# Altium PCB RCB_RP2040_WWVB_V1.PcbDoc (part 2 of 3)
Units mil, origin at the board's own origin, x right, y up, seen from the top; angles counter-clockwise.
Board outline 1250.1 x 2647.64 mil, 10 copper layers (L01-TOP, L02-GND, L03-SIG, L04-GND, L05-PWR, L06-PWR, L07-GND, L08-SIG, L09-GND, L10-BOT), stack 62.1 mil thick; 224 components, 123 nets, 635 pads, 542 vias.
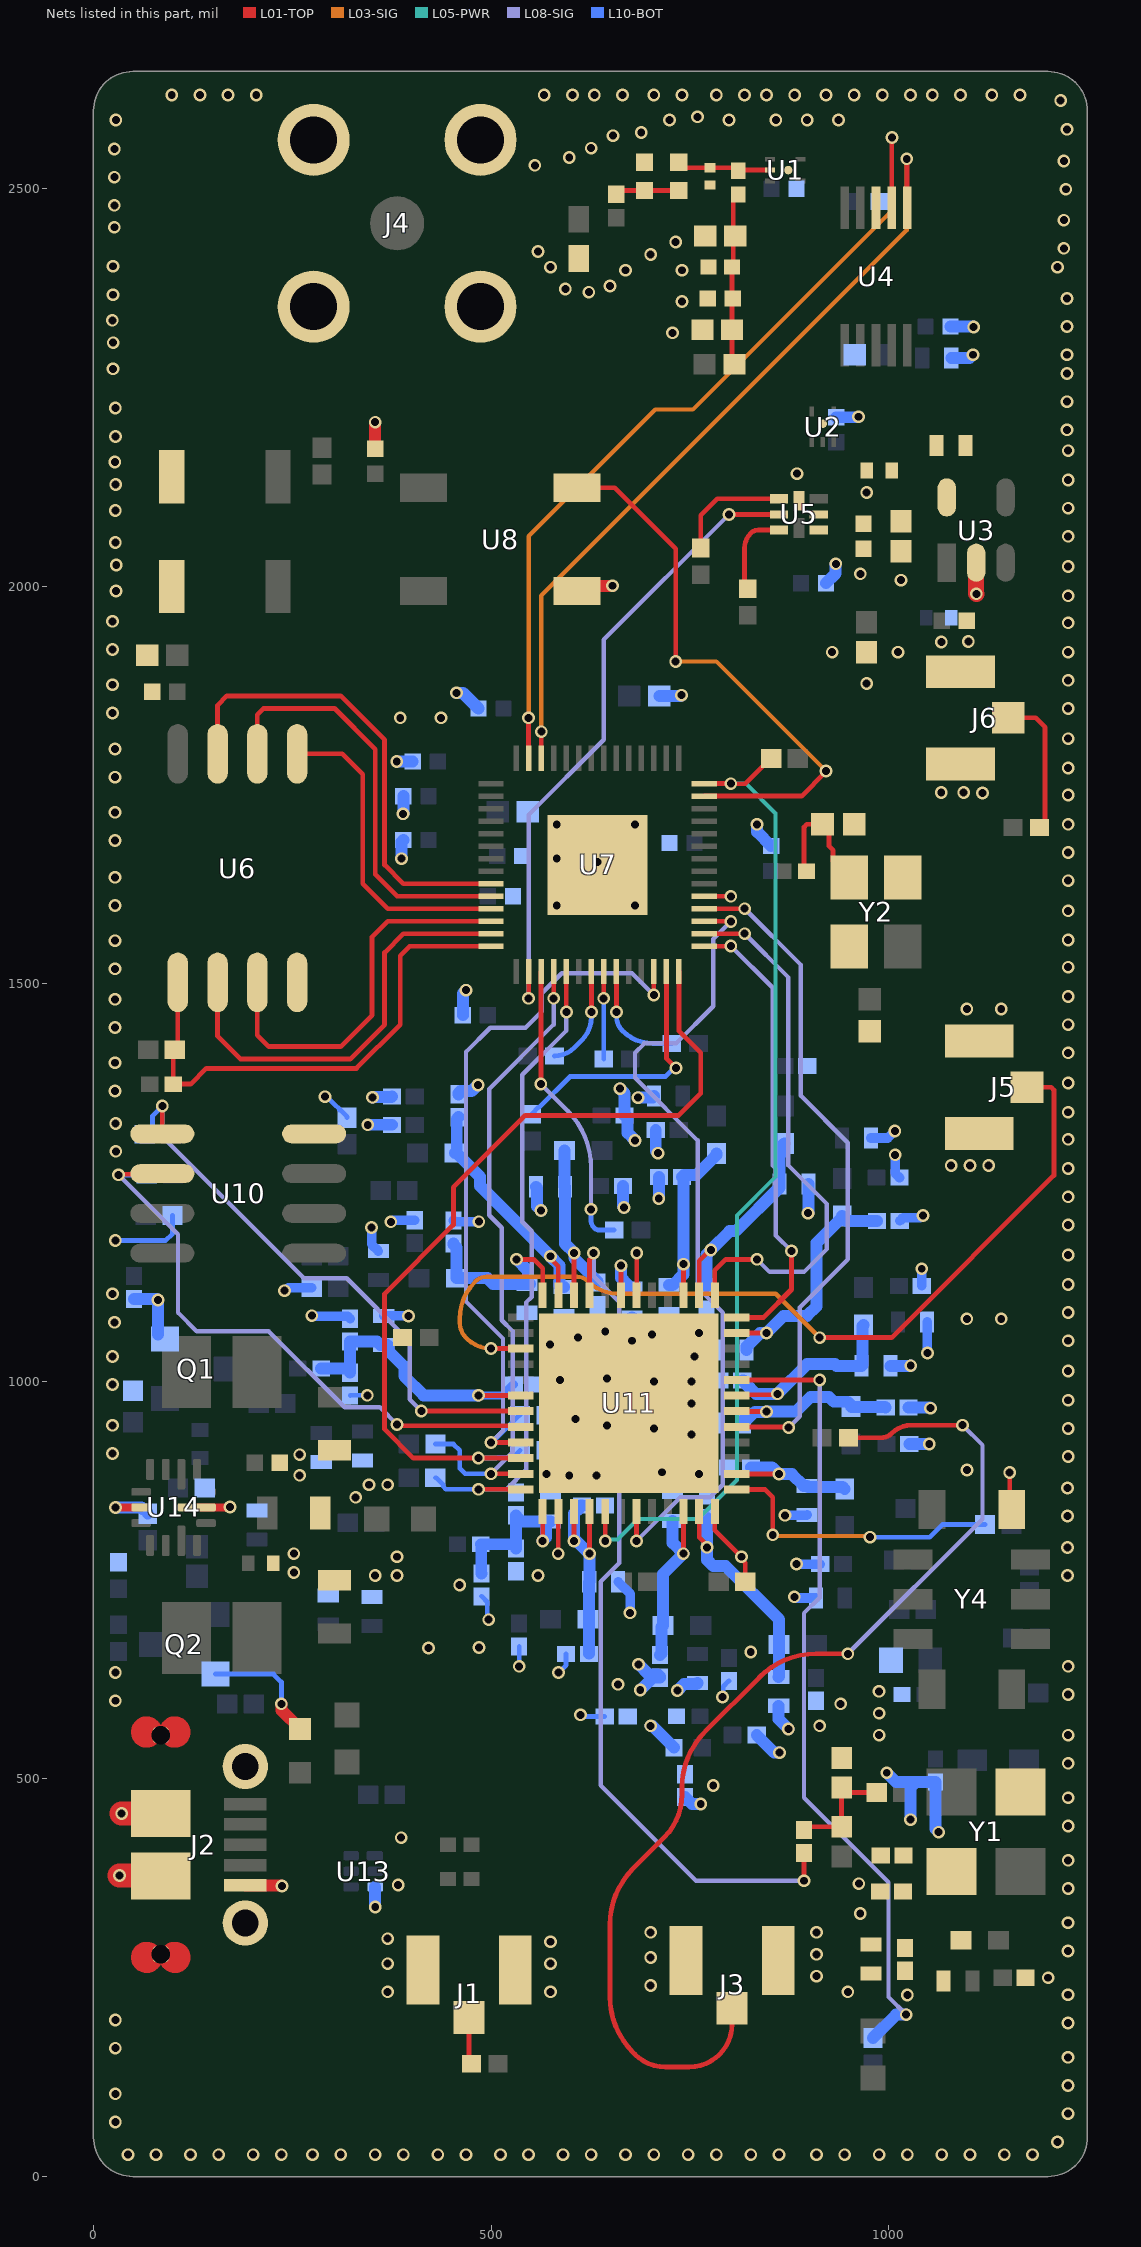
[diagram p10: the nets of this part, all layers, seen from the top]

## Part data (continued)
C8 C11 C15 C18 C28 C31 C49: library part CMP-14477-000104-2, "None", Capacitance=1uF, Case Code (Imperial)=0402, Case Code (Metric)=1005, Dielectric=X5R, Max Operating Temperature=85°C, Min Operating Temperature=-55°C, Package Quantity=1, Tolerance=10%, Voltage Rating=16V
C10 C14 C36 C37: library part CMP-2000-05997-2, "CAP CER 4.7UF 10V X5R 0402", Capacitance=4.7uF, Case Code (Imperial)=0402, Case Code (Metric)=1005, Dielectric=X5R, Dielectric Material=Ceramic, Max Operating Temperature=85°C, Min Operating Temperature=-55°C, Package Quantity=10000, Tolerance=10%, Voltage Rating=10V
C21 C23 C25 C26 C27 C55 C59 C60 C63 C65 C66 C67 C69 C70 C72 C74 C75 C76 C78 C79 C81 C82 C83 C85 C86 C88 C89 C91 C93 C95 C96 C98 C99 C101 C103 C106 C108 C110 C111 C113 C115: library part CMP-2008-02519-2, "General Purpose Ceramic Capacitor, 0402, 100nF, 10%, X7R, 15%, 25V", Capacitance=100nF, Case Code (Imperial)=0402, Case Code (Metric)=1005, Dielectric=X7R, Max Operating Temperature=125°C, Min Operating Temperature=-55°C, Package Quantity=1, Tolerance=10%, Voltage=25V
C38 C45 C48: library part CMP-2000-05441-1, "Chip Capacitor, 22 uF, +/- 20%, 10 V, -55 to 85 degC, 0603 (1608 Metric), RoHS, Tape and Reel", Capacitance=22µF, Manufacturer=TDK, Operating Temperature=-55degC~85degC, Package / Case=0603(1608Metric), Package Description="2-Pin Surface Mount Device, Body 1.6 x 0.8 mm", Package Reference=603, PCN Part Number=MLCCPartNumberChange30/Nov/2012, Ratings=-, Standard Package=1, Temperature Coefficient=X5R, Tolerance=±20%, Voltage - Rated=10V
C52 C53: library part CMP-2100-03590-1, "Chip Capacitor, 22 pF, +/- 5%, 50 V, -55 to 125 degC, 0402 (1005 Metric), RoHS, Tape and Reel", Capacitance=22pF, Case Code (Imperial)=0402, Case Code (Metric)=1005, Dielectric=C0G, Dielectric Material=Ceramic, Insulation Resistance=100GR, Manufacturer=Yageo, Max Operating Temperature=125degC, Min Operating Temperature=-55degC, Package Description="2-Pin Surface Mount Device, Body 1 x 0.5 mm", Package Quantity=1, Temperature Coefficient=30ppm/degC, Tolerance=5%, Voltage Rating=50V
C54 C57: library part CMP-2000-05393-2, "Multilayer Ceramic Capacitors 100nF ±10% 50V X7R SMD 0402", Capacitance=100nF, Case Code (Imperial)=0402, Case Code (Metric)=1005, Dielectric=X7R, Dielectric Material=Ceramic, Max Operating Temperature=125°C, Min Operating Temperature=-55°C, Package Quantity=1, Tolerance=10%, Voltage=50V
C56: library part CMP-13271-004224-1, "Cap Ceramic 10uF 25V X5R ±20% Pad SMD 0603 +85°C T/R", Capacitance=10uF, Case Code (Imperial)=0603, Case Code (Metric)=1608, Dielectric=X5R, Max Operating Temperature=85°C, Min Operating Temperature=-55°C, Package Quantity=1, Tolerance=20%, Voltage Rating=25V
C61: library part CMP-2008-02907-1, Manufacturer="AVX Interconnect / Elco", Part Number=04025C222JAT2A
C105: library part CMP-2000-06226-4, "Multilayer Ceramic Capacitor 10uF 16V X5R 20% SMD 0603 T/R", Capacitance=10uF, Case Code (Imperial)=0603, Case Code (Metric)=1608, Dielectric=X5R, Max Operating Temperature=85°C, Min Operating Temperature=-55°C, Package Quantity=1, Tolerance=20%, Voltage Rating=16V
D1 D3 D4: library part CMP-22017-000005-2, "LED GREEN CLEAR CHIP SMD", Case Code (Imperial)=0603, Case Code (Metric)=1608, Color=Green, Forward Current=30mA, Forward Voltage=2.1V, Lens Color=Colorless, Max Operating Temperature=85°C, Min Operating Temperature=-55°C, Package Quantity=1, Power Dissipation=100mW, Reverse Voltage=5V, Test Current=10mA, Voltage=2V
D2: library part CMP-1055-00495-1, "Schottky Barrier Diode, 2-Pin SOD-923, Pb-Free, Tape and Reel", Manufacturer="On Semiconductor"
D5: library part CMP-08607-000011-1, "TVS DIODE 14V 40V 0402", Breakdown Voltage=14V, Capacitance=0.25pF, Clamping Voltage=40V, Manufacturer="Littelfuse Inc.", Package=PESD0402, Temperature="-55°C to +125°C", Temperature Range High=+125°C, Temperature Range Low=-55°C
FB2: library part CMP-0220-00171-2, "FERRITE BEAD 300 OHM 0603 1LN", Case Code (Imperial)=0603, Case Code (Metric)=1608, Case/Package=SMD/SMT, Current Rating=2A, DC Resistance (DCR)=150mR, Inductance=18nH, Max Operating Temperature=125°C, Min Operating Temperature=-55°C, Package Quantity=1, Test Frequency=100MHz, Tolerance=25%
J1 J3 J5 J6: library part CMP-2000-05152-3, "CONN U.FL RCPT STR 50 OHM SMD", Dielectric Material=Polymer, Frequency=6GHz, Housing Color=Beige, Insulation Resistance=500MR, Max Operating Temperature=90°C, Min Operating Temperature=-40°C, Package Quantity=2500
J2: library part CMP-2000-05827-1, "Micro-USB B Receptacle, Right Angle, Bottom Mount, Surface Mount, with Solder Tabs, -30 to 85 degC, 5-Pin USB, RoHS, Tape and Reel", Manufacturer=Molex, Package Description="5-Leads USB, Micro B, Body 7.5 x 5 mm, Pitch 0.65 mm", Package Reference=MICRO-B, Package Version="Rev. F, 12/2012", Standard Package=1, Voltage - Max=30V
J4: library part CMP-02754-000007-1, "CONN SMA JACK STR 50 OHM SMD", Case/Package=SMA, Dielectric Material=PTFE, Housing Color=Gold, Max Frequency=20GHz, Max Operating Temperature=125°C, Min Operating Temperature=-65°C, Voltage Rating=335V
L1: library part CMP-06042-003301-1, "Multilayer type Inductor for Automotive 47nH ±5% 0.72Ω 300mA 0402", Case Code (Imperial)=0402, Case Code (Metric)=1005, Current Rating=200mA, DC Resistance (DCR)=720mR, Inductance=47nH, Max Operating Temperature=125°C, Min Operating Temperature=-55°C, Package Quantity=10000, Self Resonant Frequency=1GHz, Test Frequency=100MHz, Tolerance=5%
L2 L3 L4 L5 L6 L7 L8 L11 L12 L13 L14 L15 L16: library part CMP-0220-00137-1, "SMD EMI Suppression Ferrite Bead WE-CBF, Z = 220 Ohm"
L9 L10: library part CMP-06042-015149-1, "Shielded Wirewound Inductor 0.47uH 20% 4000mA 0.027Ω 1008 (2520)"
Q1 Q2: library part CMP-1058-00766-2, "MOSFET N-CH 60V 320MA SOT-23", Case/Package=SOT-23-3, Continuous Drain Current (ID)=320mA, Drain to Source Breakdown Voltage=60V, Drain to Source Resistance=1.6R, Gate to Source Voltage (Vgs)=20V, Input Capacitance=24.5pF, Max Operating Temperature=150°C, Max Power Dissipation=420mW, Min Operating Temperature=-55°C, Package Quantity=1, Power Dissipation=300mW, Threshold Voltage=2.3V
R1 R2 R48: library part CMP-2002-08277-1, Manufacturer="Vishay Dale", Part Number=CRCW04021K00FKTD
R3 R4 R5 R8: library part CMP-2002-06458-1, Manufacturer=Panasonic, Part Number=ERJ-U02F1000X
R6 R33 R34 R35 R36 R37 R38 R39 R40 R41 R42 R44 R79 R97: library part CMP-2002-06457-1, Manufacturer=Panasonic, Part Number=ERJ-U020R00X
R7 R26: library part CMP-2002-04448-1, Manufacturer="KOA Speer", Part Number=RK73H1ETTP49R9F
R9 R13 R53 R54 R56 R77: library part CMP-2002-04694-1, Manufacturer=Bourns, Part Number=CR0402-FX-1002GLF
R10 R14: library part CMP-2002-04692-1, Manufacturer=Bourns, Part Number=CR0402-FX-1001GLF
R11 R12: library part CMP-2002-07055-1, Manufacturer="Yageo / Phycomp", Part Number=RC0402FR-0727RL
R15: library part CMP-2002-05709-1, Manufacturer="TE Connectivity / AMP", Part Number=CRG0402F20K
R16 R17 R71: library part CMP-2002-05853-1, Manufacturer=Panasonic, Part Number=ERA-2AED331X
R18 R19 R20 R21 R22 R23 R24 R25 R27 R28 R29 R30 R31 R32 R45 R46 R49 R50 R95 R96: library part CMP-2002-05217-1, Manufacturer=Bourns, Part Number=CR0402-FX-4701GLF
R47 R51 R52: library part CMP-2002-04569-1, Manufacturer="KOA Speer", Part Number=RK73Z1ETTP
R58: library part CMP-1011-00697-1, "45K3 0.063W 1% 0402 (1005 Metric)  SMD", Case-EIA=0402, Case-Metric=1005, Power="0.063 W", Tolerance="1 %"
R98: library part CMP-2002-00253-3, "Chip Resistor, 8.06 KOhm, +/- 1%, 63 mW, -55 to 155 degC, 0402 (1005 Metric), RoHS, Tape and Reel", Case Code (Imperial)=0402, Case Code (Metric)=1005, Manufacturer="Basic Passives", Max Operating Temperature="155 degC", Min Operating Temperature="-55 degC", Package Quantity=10000, PartNumber=CRCW04028K06FKED, Power Rating="63 mW", Resistance="8.06 KOhm", Tolerance=1%, Voltage Rating="50 V"
SW1 SW2: library part CMP-2100-03586-2, "SWITCH TACTILE SPST-NO 0.05A 12V", Contact Current Rating=50mA, Contact Resistance=100mR, Insulation Resistance=100MR, Max Operating Temperature=70°C, Max Voltage Rating (DC)=12V, Min Operating Temperature=-25°C, Operating Force=1.5N, Package Quantity=1, Ratings="Dust Proof"
U1 U2: library part CMP-85923-000009-1, "IC RF SWITCH SPDT 6GHZ 6MLPD", Max Operating Temperature=90°C, Min Operating Temperature=-40°C, Test Frequency=2.5GHz
U3: library part CMP-79890-000003-1, "IC REG LIN 3.3V 600MA TSOT23-5", Case/Package=SOT-23-5, Dropout Voltage=530mV, Max Input Voltage=5.5V, Max Operating Temperature=85°C, Min Operating Temperature=-40°C, Min Output Voltage=3.3V, Output Current=600mA, Power Supply Rejection Ratio (PSRR)=75dB, Quiescent Current=4uA
U4: "No Description Available", Mfr_Name="Analog Devices Inc"
U5: "No Description Available", Mfr_Name="Texas Instruments"
U6: library part CMP-2000-05005-1, "3V 128M-Bit Serial Flash Memory with Dual/Quad SPI & QPI, 2.7 to 3.6 V, -40 to 85 degC, 8-Pin SOIC, RoHS, Tape and Reel", Manufacturer=Winbond, Operating Supply Voltage (Max)=3.6V, Operating Supply Voltage (Min)=2.7V, Operating Supply Voltage (Typ)=3/3.3V, Operating Temp Range=-40Cto85C, Operating Temperature (Max)=85C, Operating Temperature (Min)=-40C, Operating Temperature Classification=Industrial, Package Description="8-Pin Small Outline Integrated Circuit, Body 5.28 x 5.28 mm, Pitch 1.27 mm", Package Reference=SS-8, Package Type=SOICW, Program/Erase Volt (Typ)=2.7to3.6V, Supply Current=20mA
U7: "No Description Available", Mfr_Name="Raspberry Pi"
U8: library part CMP-2000-05026-1, "Intelligent Control LED Integrated Light Source, 3.5 to 5.3 V, -25 to 80 degC, 4-Pin SMD, RoHS, Tape and Reel", Color=Red,Green,Blue(RGB), Manufacturer=Adafruit-Industries-LLC, Package Description="4-Pin Surface Mount Device, Body 5 x 5 mm"
U10: library part CMP-0159-01024-1, "1024K bits I2C™ Serial EEPROM, 2.5 to 5.5 V, 400 kHz, -40 to 85 degC, 8-pin SOIC (SN8), Tube", Manufacturer=Microchip
U11: "No Description Available", Mfr_Name="Renesas Electronics"
U13: library part CMP-0326-00032-3, "Low-Capacitance + / - 15 kV ESD-Protection Array for High-Speed Data Interfaces, 3 Channels, -40 to +85 degC, 6-pin SON (DRY), Green (RoHS & no Sb/Br)", Breakdown Voltage(Min)(V)=11, IO Capacitance(Typ)(pF)=1.5, IO Leakage Current(nA)=Jan-00, Manufacturer="Texas Instruments"
U14: library part CMP-04918-000654-1, "Adjustable-Frequency Dual Step-Down Converter, 2.7-6V VIN, 0.6-5.5V 2A VOUT, VQFN-HR14"
Y1: library part CMP-25159-259584-1, "MEMS OSC TCXO 40.0000MHZ LVCMOS", Case/Package=SMD/SMT, Frequency=40MHz, Frequency Stability=5ppm, Max Operating Temperature=70°C, Max Supply Current=33mA, Min Operating Temperature=-20°C
Y2: library part CMP-2000-05039-3, "Crystal 12MHz ±20ppm (Tol) ±30ppm (Stability) 18pF FUND 120Ω 4-Pin SMD T/R", Case/Package=CSMD, ESR (Equivalent Series Resistance)=120R, Frequency=12MHz, Frequency Stability=30ppm, Frequency Tolerance=20ppm, Load Capacitance=18pF, Max Operating Temperature=85°C, Min Operating Temperature=-40°C, Operating Frequency="12 MHz", Package Quantity=1000
Y4: library part CMP-OSC-00029-2, "OSC, MEMS, STRATUM 3E, 10.000MHZ, 10PPB STAB, LVCMOS, 3.3V, O/P EN, 7.0X5.0X2.2MM, CQFN-10", Case/Package="10 Lead QFN", Frequency="10 MHz", Frequency Stability="±10 ppb", Manufacturer=SiTime, Manufacturer Part Number=SiT5501AI-WU033JH-10.000000, Max Operating Temperature=70°C, Min Operating Temperature=-20°C, Voltage - Supply="3.3 V"

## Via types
v1: diameter 16, hole 10, L01-TOP to L10-BOT, tented both sides, 542 vias

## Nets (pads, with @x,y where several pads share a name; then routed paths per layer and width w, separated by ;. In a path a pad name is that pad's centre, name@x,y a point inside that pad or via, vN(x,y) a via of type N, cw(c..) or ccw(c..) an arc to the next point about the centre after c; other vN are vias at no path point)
ADC_AVDD: C13.1 C14.1 C15.1 C16.1 U3.5 U5.6
ADC_SDO: U5.2 U7.2 | length 809.6
  L01-TOP w6: v1(547.26,1481.95) 547.34,1482.03 U7.2@547.34,1515.56 ; v1(799.21,2090.55) U5.2@862.2,2090.55
  L08-SIG w5.5: v1(547.26,1481.95) 547.26,1712.61 641.73,1807.09 641.73,1933.07 v1(799.21,2090.55)
AMP_DIN: U4.2 U7.41 | length 1086.1
  L01-TOP w6: v1(547.24,1834.65) 547.31,1834.57 547.31,1783.68 U7.41@547.39,1783.61 ; U4.2@1003.94,2476.51 1003.94,2564.07 v1(1004.35,2564.48)
  L03-SIG w5.5: v1(547.24,1834.65) 547.24,2062.99 706.69,2222.44 753.94,2222.44 1004.35,2472.85 v1(1004.35,2564.48)
AMP_SCLK: U4.1 U7.40 | length 1006.2
  L01-TOP w6: U7.40@563.18,1783.65 563.18,1817.18 v1(563.26,1817.27) ; v1(1022.91,2537.83) 1023.26,2537.47 1023.26,2476.87 U4.1@1023.62,2476.51
  L03-SIG w5.5: v1(563.26,1817.27) 563.26,1988.46 1022.91,2448.1 v1(1022.91,2537.83)
DPLL_CLKIN0_N: J5.1 U11.3 | length 1138.7
  L01-TOP w6: v1(500,1041.34) U11.3@537.23,1041.34 ; v1(913.39,1055.12) 1003.94,1055.12 1207.98,1259.16 1207.98,1366.56 1204.46,1370.08 J5.1@1174.21,1370.08
  L03-SIG w5.5: 480.32,1125.98 cw(c494.01,1112.29) 494.01,1131.66 608.35,1131.66 cw(c608.35,1112.29) 622.05,1125.98 ccw(c660.07,1164) 660.07,1110.24 858.27,1110.24 v1(913.39,1055.12) ; 482.65,1127.98 479.87,1125.2 ccw(c526.33,1078.74) 460.63,1078.74 460.63,1074.13 ccw(c487.51,1074.13) 468.5,1055.12 469.76,1053.87 ccw(c500,1084.11) v1(500,1041.34)
DPLL_CLKIN0_P: R34.1
DPLL_CLKIN1_N: J1.1 R44.1 | length 59.3
  L01-TOP w6: J1.1@472.44,199.8 472.44,144.69 R44.1@475.39,141.73
DPLL_CLKIN1_P: R36.1 U7.13 | length 332.1
  L01-TOP w6: U7.13@720.73,1515.58 720.61,1515.46 720.61,1406.35 v1(732.79,1394.18)
  L10-BOT w6: R36.1@551.85,1336.02 551.85,1337 559.68,1344.83 560.66,1344.83 599.36,1383.52 719.43,1383.52 730.08,1394.18 v1(732.79,1394.18)
DPLL_CLKOUT8_N: R33.2 U5.1 | length 148.2
  L01-TOP w6: R33.2@763.78,2048.23 763.78,2089.33 784.69,2110.24 U5.1@862.2,2110.24
DPLL_CLKOUT8_P: R39.2 U7.3 | length 371.6
  L01-TOP w6: v1(562.68,1374.02) 562.91,1374.24 562.91,1515.24 U7.3@563.25,1515.58
  L08-SIG w5.5: v1(562.68,1374.02) 596.43,1340.26 cw(c525.72,1269.55) 625.72,1269.55 v1(625.72,1216.54)
  L10-BOT w6: v1(625.72,1216.54) 625.72,1203.05 ccw(c640.06,1203.05) 629.92,1192.91 ccw(c635.82,1198.81) 635.82,1190.47 R39.2@655.07,1190.47
DPLL_CLKOUT9_N: R35.2 U5.3 | length 109.5
  L01-TOP w6: R35.2@822.83,1997.05 cw(c832.34,2006.55) 818.9,2006.55 818.9,2047.92 cw(c845.78,2047.92) 826.77,2066.93 cw(c836.28,2057.42) 836.28,2070.87 U5.3@862.2,2070.87
DPLL_CLKOUT9_P: R40.2 U7.8 | length 110.1
  L01-TOP w6: v1(641.74,1481.95) 641.83,1482.03 U7.8@641.83,1515.56
  L10-BOT w6: R40.2@641.73,1405.51 v1(641.74,1481.95)
DPLL_CLKOUT10_N: J3.1 R37.2 | length 1360.9
  L01-TOP w6: J3.1@803.15,211.61 803.15,191.56 cw(c749.38,191.56) 787.4,153.54 cw(c749.38,191.56) 749.38,137.8 719.12,137.8 cw(c719.12,191.56) 681.1,153.54 678.9,155.75 cw(c749.61,226.46) 649.61,226.46 649.61,316.85 cw(c749.61,316.85) 678.9,387.56 717.89,426.55 ccw(c664.12,480.32) 740.16,480.32 740.16,489.09 cw(c840.16,489.09) 769.45,559.8 837.84,628.19 cw(c908.55,557.48) 908.55,657.48 v1(948.82,657.48) ; R37.2@949.8,929.13 990.46,929.13 ccw(c990.46,948.19) 1003.94,934.71 cw(c1028.89,909.76) 1028.89,945.05 v1(1093.03,945.05)
  L08-SIG w5.5: v1(948.82,657.48) 1118.11,826.77 1118.11,919.97 v1(1093.03,945.05)
DPLL_CLKOUT10_P: R41.2 U7.9 | length 143
  L01-TOP w6: U7.9@657.74,1515.72 657.74,1464.82 v1(657.81,1464.75)
  L10-BOT w6: v1(657.81,1464.75) 657.81,1459.16 ccw(c683.57,1459.16) 665.35,1440.94 ccw(c703.37,1478.96) 703.37,1425.2 R41.2@727.36,1425.2
DPLL_CLKOUT11_N: J6.1 R38.2 | length 180
  L01-TOP w6: J6.1@1150.59,1834.65 1185.04,1834.65 1196.85,1822.83 1196.85,1703.74 R38.2@1189.96,1696.85
DPLL_CLKOUT11_P: R42.2 U7.7 | length 130.8
  L01-TOP w6: U7.7@626.24,1515.58 626.24,1464.68 v1(626.31,1464.61)
  L10-BOT w6: R42.2@579.72,1409.45 ccw(c579.72,1445.09) 604.93,1419.89 614.17,1429.13 ccw(c584.87,1458.44) 626.31,1458.44 v1(626.31,1464.61)
DPLL_CREG_XTAL: C58.1 U11.43 | length 74.6
  L01-TOP w6: U11.43@663.39,1108.44 v1(663.39,1145.67)
  L10-BOT w15: v1(663.39,1145.67) 663.58,1145.48 663.58,1130.22 671.38,1122.42 671.38,1117.99 672.74,1116.63 C58.1@677.17,1116.63
DPLL_CS: R46.1 U7.12 U11.9 | length 940.5
  L01-TOP w6: v1(499.89,923.23) U11.9@537.12,923.23 ; v1(704.74,1486.03) 704.82,1486.11 U7.12@704.82,1519.64
  L08-SIG w5.5: v1(499.89,923.23) 515.05,938.39 515.05,1054.01 468.5,1100.56 468.5,1414.46 498.93,1444.88 543.31,1444.88 563.7,1465.28 563.7,1488.18 588.92,1513.4 677.37,1513.4 v1(704.74,1486.03)
  L10-BOT w6: v1(499.89,923.23) 501.14,923.23 535.51,957.6 R46.1@536.5,957.6
DPLL_EEPROM_SCL: R19.2 U10.6 U11.8 | length 786
  L01-TOP w6: v1(31.5,1259.84) 32.28,1260.63 85.83,1260.63 U10.6@86.61,1261.42 ; v1(381.89,945.87) 383.37,944.39 535.75,944.39 U11.8@537.12,943.02
  L08-SIG w5.5: v1(31.5,1259.84) 106.3,1185.04 106.3,1086.61 129.92,1062.99 220.47,1062.99 315.95,967.52 360.24,967.52 v1(381.89,945.87)
  L10-BOT w6: v1(31.5,1259.84) 66.07,1259.84 R19.2@66.86,1260.63
DPLL_EEPROM_SDA: R18.2 U10.5 U11.7 | length 755.2
  L01-TOP w6: U10.5@86.61,1311.42 v1(86.61,1346.46) ; v1(412.35,962.9) 412.5,962.75 537.08,962.75 U11.7@537.23,962.6
  L08-SIG w5.5: v1(86.61,1346.46) 86.61,1308.03 264.72,1129.92 318.43,1129.92 397.64,1050.72 397.64,977.61 v1(412.35,962.9)
  L10-BOT w6: R18.2@64.53,1310.97 65.52,1310.97 74.33,1319.78 74.33,1334.17 v1(86.61,1346.46)
DPLL_FILTER: C59.1 C60.1 R47.2 R48.2 U11.14 | length 94.1
  L01-TOP w6: v1(584.43,783.38) 584.54,783.49 584.54,836.33 U11.14@584.65,836.44
  L10-BOT w15: v1(700.79,566.93) 700.98,566.74 702.95,566.74 R48.2@730.31,539.37
DPLL_GPIO0: U11.42 | length 53
  L01-TOP w6: U11.42@683.18,1108.55 683.18,1161.39 v1(683.29,1161.5)
DPLL_GPIO1: R71.1 U11.32 | length 1017.9
  L01-TOP w6: U11.32@809.34,1001.86 809.44,1001.97 v1(913.39,1001.97)
  L08-SIG w5.5: v1(913.39,1001.97) 913.39,728.35 893.7,708.66 893.7,476.38 1000,370.08 1000,225.73 v1(1022.2,203.53)
  L10-BOT w15: R71.1@980.31,174.21 1009.64,203.53 v1(1022.2,203.53)
DPLL_GPIO2: U7.18 U11.29 | length 853.6
  L01-TOP w6: U7.18@768.03,1594.6 818.92,1594.6 v1(819,1594.67) ; U11.29@809.23,942.91 809.59,942.55 874.07,942.55 v1(874.43,942.18)
  L08-SIG w5.5: v1(819,1594.67) 889.76,1523.91 889.76,1359.27 948.82,1300.22 948.82,1153.54 888.28,1093.01 888.28,956.03 v1(874.43,942.18)
DPLL_GPIO3: U7.17 U11.19 | length 1036
  L01-TOP w6: v1(683.07,799.21) U11.19@683.07,836.44 ; U7.17@768,1578.74 801.57,1578.7 v1(801.66,1578.61)
  L08-SIG w5.5: v1(683.07,799.21) 738.19,854.33 775.59,854.33 791.34,870.08 791.34,1086.61 759.84,1118.11 759.84,1303.15 681.1,1381.89 681.1,1413.39 692.91,1425.2 732.79,1425.2 779.53,1471.94 779.53,1556.48 v1(801.66,1578.61)
DPLL_GPIO4: U7.16 U11.37 | length 686.9
  L01-TOP w6: U7.16@768.03,1563.11 818.92,1563.11 v1(819,1563.18) ; U11.37@781.5,1108.44 781.5,1139.76 795.28,1153.54 v1(834.65,1153.54)
  L08-SIG w5.5: v1(819,1563.18) 874.02,1508.16 874.02,1271.65 922.49,1223.18 922.49,1166.59 893.7,1137.8 850.39,1137.8 v1(834.65,1153.54)
DPLL_GPIO5: U7.15 U11.36 | length 580.8
  L01-TOP w6: U7.15@768,1547.24 768.28,1547.53 801.36,1547.53 v1(801.64,1547.81) ; U11.36@809.34,1080.6 842.9,1080.6 877.95,1115.65 v1(877.95,1163.97)
  L08-SIG w5.5: v1(801.64,1547.81) 854.33,1495.12 854.33,1271.65 858.27,1267.72 858.27,1183.66 v1(877.95,1163.97)
DPLL_GPIO8: R23.2 U11.25 | length 371.2
  L01-TOP w6: U11.25@809.23,864.17 844.49,864.17 854.33,854.33 v1(854.33,807.09)
  L03-SIG w5.5: v1(854.33,807.09) 855.81,805.61 975.12,805.61 v1(976.6,804.13)
  L10-BOT w6: v1(976.6,804.13) 1051.77,804.13 1067.66,820.02 R23.2@1121.26,820.02
DPLL_GPIO9: R22.2 U11.24 | length 104.2
  L01-TOP w6: U11.24@781.39,836.33 781.39,813.1 v1(814.96,779.53) 814.96,776.82 819.88,771.9 R22.2@819.88,748.03
DPLL_OSCI: C21.2 U11.45 | length 1101.2
  L01-TOP w6: U11.45@624.02,1108.44 624.02,1153.79 629.02,1158.79 v1(629.02,1161.5) ; v1(893.63,372.04) 893.7,372.1 C21.2@893.7,406.87
  L08-SIG w5.5: v1(629.02,1161.5) 629.02,1132.21 661.42,1099.81 661.42,1039.37 677.17,1023.62 677.17,940.94 661.42,925.2 661.42,771.65 637.8,748.03 637.8,492.13 757.88,372.04 v1(893.63,372.04)
DPLL_RST_N: R31.1 U7.28 U11.17 | length 1262.5
  L01-TOP w6: v1(643.7,799.21) U11.17@643.7,836.44 ; U7.28@768,1751.97 801.57,1751.92 v1(801.66,1751.84) 819.75,1751.84 851.38,1783.46 R31.1@852.36,1783.46
  L05-PWR w5: v1(643.7,799.21) 645.42,800.93 659.2,800.93 685.04,826.77 760.09,826.77 809.18,875.87 809.18,1208.66 857.99,1257.47 857.99,1714.46 820.62,1751.84 v1(801.66,1751.84)
DPLL_SCLK: R49.1 U7.5 U11.12 | length 841.9
  L01-TOP w6: v1(484.17,864.39) 484.28,864.28 U11.12@537.12,864.28 ; U7.5@594.74,1515.58 594.74,1464.68 v1(594.82,1464.61)
  L08-SIG w5.5: v1(484.17,864.39) 519.66,864.39 544.13,888.86 544.13,1099.24 551.18,1106.3 551.18,1188.98 539.37,1200.79 539.37,1385.83 594.82,1441.27 v1(594.82,1464.61)
  L10-BOT w6: R49.1@430.04,878.76 431.02,878.76 439.84,869.95 439.84,867.9 443.35,864.39 v1(484.17,864.39)
DPLL_SDI: R45.1 U7.14 U11.10 | length 1107
  L01-TOP w6: U11.10@537.01,903.65 402.47,903.65 366.16,939.96 366.16,1110.25 452.76,1196.85 452.76,1244.09 543.31,1334.65 736.22,1334.65 763.78,1362.2 763.78,1413.39 736.32,1440.85 U7.14@736.32,1515.56
  L10-BOT w6: v1(484.06,903.76) 507.28,903.76 508.1,904.57 527.68,904.57 R45.1@536.5,913.39
DPLL_SDIO: R50.1 U7.4 U11.11 | length 829.8
  L01-TOP w6: v1(500,883.86) U11.11@537.23,883.86 ; v1(578.75,1481.95) 578.84,1482.03 U7.4@578.84,1515.56
  L08-SIG w5.5: v1(500,883.86) 527.12,910.98 527.12,999.03 ; 527.12,993.95 527.12,999.03 ; v1(578.75,1481.95) 578.75,1448.83 497.72,1367.8 497.72,1209.18 513.56,1193.33 513.56,1076.97 527.12,1063.41 527.12,999.03
  L10-BOT w6: R50.1@430.12,921.26 452.76,921.26 460.63,913.39 460.63,890.57 467.35,883.86 v1(500,883.86)
DPLL_VDD_CLK: C94.1 C95.1 L11.2 U11.48 | length 251.2
  L01-TOP w6: v1(532.13,1153.54) 553.9,1153.54 565.07,1142.37 U11.48@565.07,1108.55
  L10-BOT w15: C95.1@452.61,1173.67 452.61,1172.31 456.69,1168.23 L11.2@456.69,1129.92 495.34,1129.92 502.46,1122.8 549.34,1122.8 547.87,1122.8 546.51,1124.16 546.51,1139.16 v1(532.13,1153.54)
DPLL_VDD_DCO_Q8: C62.1 C63.1 L4.2 U11.38 | length 288.5
  L01-TOP w6: U11.38@761.92,1108.55 761.92,1151.65 775.62,1165.35 v1(776.5,1165.35)
  L10-BOT w15: C63.1@771.1,1119.28 771.1,1159.69 776.5,1165.08 v1(776.5,1165.35) 800.12,1188.98 807.85,1188.98 862.86,1243.99 C62.1@862.86,1248.42 862.86,1284.2 864.73,1286.07 864.73,1295.04 L4.2@869.04,1299.35
DPLL_VDD_DCO_Q9: C77.1 C78.1 L5.2 U11.31 | length 278.2
  L01-TOP w6: U11.31@809.23,982.28 810.32,983.38 859.23,983.38 v1(860.33,984.47)
  L10-BOT w15: C78.1@816.12,1001.39 817.47,1001.39 820.05,998.81 820.05,997.45 833.03,984.47 v1(860.33,984.47) 897.63,1021.77 932.6,1021.77 934.68,1019.68 C77.1@966.04,1019.68 967.27,1020.92 967.27,1069.64 L5.2@968.5,1070.87
DPLL_VDD_DCO_Q10: C87.1 C88.1 L7.2 U11.30 | length 236.1
  L01-TOP w6: U11.30@811.41,962.6 811.72,962.29 846.15,962.29 v1(846.46,961.98)
  L10-BOT w15: C87.1@817.93,947.91 817.93,952.34 819.29,953.7 823.72,953.7 831.81,961.79 846.27,961.79 v1(846.46,961.98) 883.24,961.98 901.57,980.32 925.2,980.32 931.05,974.46 948.44,974.46 952.76,970.15 L7.2@952.76,968.67 953.45,967.98 995.71,967.98 C88.1@996.4,967.29
DPLL_VDD_DCO_Q11: C97.1 C98.1 L12.2 U11.23 | length 295.7
  L01-TOP w6: U11.23@761.81,836.44 761.81,803.89 771.65,794.04 v1(771.65,791.34)
  L10-BOT w15: C98.1@771.65,828.13 v1(771.65,791.34) 771.84,791.15 771.84,775.4 779.53,767.72 795.28,767.72 862.2,700.79 L12.2@862.2,669.29 862.02,669.11 862.02,628.72 C97.1@861.84,628.53
DPLL_VDD_DIG: C64.1 C65.1 C66.1 C67.1 R51.2 U11.6 | length 381.7
  L01-TOP w6: v1(484.17,982.5) 484.28,982.39 U11.6@537.12,982.39
  L10-BOT w10: v1(484.17,982.5) 484.28,982.6 514.1,982.6 527.56,996.06 C65.1@528.92,996.06
  L10-BOT w15: R51.2@286.42,1016.31 318.9,1016.31 322.83,1012.37 C67.1@322.83,1011.01 322.88,1011.06 C66.1@322.92,1050.13 C66.1@322.92,1050.13 356.57,1050.13 360.67,1046.03 369.53,1046.03 370.89,1044.67 370.89,1038.67 391.01,1018.56 391.01,1006.63 415.14,982.5 v1(484.17,982.5)
DPLL_VDD_GPIO: C80.1 C81.1 C82.1 C83.1 R52.2 U11.13 | length 235
  L01-TOP w6: v1(564.96,799.21) U11.13@564.96,836.44
  L10-BOT w15: C83.1@488.19,758.49 487.7,758.98 487.7,794.78 R52.2@487.2,795.28 527.56,795.28 C82.1@531.5,791.34 ; C82.1@531.5,789.98 C82.1@531.5,791.34 ; C81.1@531.5,831.68 C81.1@531.5,830.33 ; v1(564.96,799.21) 564.96,799.48 569.02,803.54 569.02,822.63 C80.1@570.37,823.99 ; C80.1@574.8,823.99 C80.1@570.37,823.99 ; C82.1@531.5,791.34 C81.1@531.5,830.33 ; C81.1@531.5,830.33 537.83,823.99 C80.1@570.37,823.99
DPLL_VDDA_BG_LC: C68.1 C69.1 C70.1 L3.2 U11.15 U11.16 | length 292
  L01-TOP w6: v1(604.33,799.21) U11.15@604.33,836.44 ; v1(623.8,783.38) 623.91,783.49 U11.16@623.91,836.33
  L10-BOT w15: C69.1@614.62,843.97 613.27,843.97 610.69,841.39 610.69,840.04 604.33,833.68 v1(604.33,799.21) 604.52,799.02 607.89,799.02 623.53,783.38 v1(623.8,783.38) ; C70.1@623.15,657.48 623.34,657.67 623.34,747.85 C68.1@623.52,748.03 623.66,748.17 v1@623.66,783.24
DPLL_VDDA_FB: C109.1 C110.1 L15.2 U11.47 | length 328.5
  L01-TOP w6: v1(574.8,1157.48) 574.8,1154.77 584.65,1144.93 U11.47@584.65,1108.44
  L10-BOT w15: C110.1@458.98,1332.37 456.88,1330.27 456.88,1289.5 L15.2@454.78,1287.4 456.26,1287.4 486.19,1257.47 486.19,1246.09 v1(574.8,1157.48) 574.8,1157.21 586.07,1145.94 586.07,1120.36 587.43,1119.01 C109.1@591.86,1119.01
DPLL_VDDA_PDCP_XTAL: C84.1 C85.1 L6.2 U11.46 | length 236.3
  L01-TOP w6: U11.46@604.44,1108.55 604.44,1161.39 v1(604.55,1161.5)
  L10-BOT w15: L6.2@592.27,1290.64 592.68,1290.23 592.68,1245.34 C84.1@593.08,1244.94 593.08,1173.23 604.55,1161.77 v1(604.55,1161.5) 604.74,1161.31 604.74,1155.02 633.86,1125.9 C85.1@633.86,1124.54
DPLL_VDDO_Q8: C102.1 C103.1 L13.2 U11.39 | length 240.6
  L01-TOP w6: U11.39@742.13,1110.24 v1(742.13,1147.46)
  L10-BOT w15: C102.1@724.05,1121.12 728.48,1121.12 741.93,1134.57 741.93,1147.27 v1(742.13,1147.46) 741.93,1147.66 741.93,1255.28 C103.1@740.19,1257.03 742.77,1259.61 758.32,1259.61 783.72,1285.02 L13.2@783.72,1286.49
DPLL_VDDO_Q9: C92.1 C93.1 L8.2 U11.35 | length 323.4
  L01-TOP w6: U11.35@809.23,1061.02 v1(846.46,1061.02)
  L10-BOT w15: C92.1@821.36,1039.37 821.36,1043.8 838.39,1060.83 846.27,1060.83 v1(846.46,1061.02) 846.73,1061.02 868.13,1082.43 897.39,1082.43 909.45,1094.49 909.45,1174.46 L8.2@941.69,1206.69 ; L8.2@941.69,1208.17 L8.2@941.69,1206.69 ; C93.1@985.41,1202.03 947.83,1202.03 947.47,1202.38 946,1202.38 L8.2@941.69,1206.69
DPLL_VDDO_Q10: C114.1 C115.1 L16.2 U11.26 | length 182
  L01-TOP w6: U11.26@809.34,883.75 862.18,883.75 v1(862.29,883.64)
  L10-BOT w15: C115.1@827.2,892.05 853.61,892.05 862.02,883.64 v1(862.29,883.64) 862.48,883.45 878.36,883.45 893.21,868.6 C114.1@897.64,868.6 899,867.24 942.3,867.24 L16.2@944.88,864.67
DPLL_VDDO_Q11: C107.1 C108.1 L14.2 U11.22 | length 238.9
  L01-TOP w6: v1(741.91,783.38) 742.02,783.49 U11.22@742.02,836.33
  L10-BOT w15: C108.1@712.6,656.12 714.57,658.09 714.57,690.94 L14.2@716.54,692.91 716.54,758.01 v1(741.91,783.38) 728.35,796.95 C107.1@728.35,824.31
FLASH_CS: R9.2 R10.2 U6.1 U7.56 | length 652.4
  L01-TOP w6: U6.1@106.1,1501.97 106.1,1421.06 R9.2@102.36,1417.32 100.39,1415.35 R10.2@100.39,1374.02 122.05,1374.02 141.73,1393.7 330.71,1393.7 385.83,1448.82 385.83,1535.43 397.64,1547.24 U7.56@500,1547.24
FLASH_IO0: U6.5 U7.53 | length 405.3
  L01-TOP w6: U6.5@256.1,1789.37 312.99,1789.37 338.58,1763.78 338.58,1625.98 370.08,1594.49 U7.53@500,1594.49
FLASH_IO1: U6.2 U7.55 | length 541.7
  L01-TOP w6: U6.2@156.1,1501.97 156.1,1434.45 185.04,1405.51 322.83,1405.51 366.14,1448.82 366.14,1539.37 389.76,1562.99 U7.55@500,1562.99
FLASH_IO2: U6.3 U7.54 | length 489.1
  L01-TOP w6: U6.3@206.1,1501.97 206.1,1435.63 220.47,1421.26 311.02,1421.26 350.39,1460.63 350.39,1559.06 370.08,1578.74 U7.54@500,1578.74
FLASH_IO3: U6.7 U7.51 | length 599.9
  L01-TOP w6: U6.7@156.1,1789.37 156.1,1850.39 167.91,1862.2 311.02,1862.2 366.14,1807.09 366.14,1649.61 389.76,1625.98 U7.51@500,1625.98
FLASH_SCK: U6.6 U7.52 | length 536.5
  L01-TOP w6: U6.6@206.1,1789.37 206.1,1838.58 213.98,1846.46 303.15,1846.46 354.33,1795.28 354.33,1637.8 381.89,1610.24 U7.52@500,1610.24
GND: C1.2 C3.1 C4.2 C5.2 C6.1 C7.1 C8.2 C9.2 C10.2 C11.2 C12.2 C13.2 C14.2 C15.2 C16.2 C17.2 C18.2 C19.2 C20.2 C22.2 C23.2 C24.2 C25.2 C26.2 C27.2 C28.2 C29.2 C30.2 C31.2 C32.2 C33.2 C34.2 C35.2 C36.2 C37.2 C38.1 C39.2 C40.2 C41.2 C42.2 C43.2 C44.2 C45.1 C46.2 C47.2 C48.1 C49.2 C50.2 C51.2 C52.1 C53.1 C54.1 C55.2 C56.2 C57.1 C58.2 C59.2 C60.2 C61.1 C62.2 C63.2 C64.2 C65.2 C66.2 C67.2 C68.2 C69.2 C70.2 C71.2 C72.2 C73.2 C74.2 C75.2 C76.2 C77.2 C78.2 C79.2 C80.2 C81.2 C82.2 C83.2 C84.2 C85.2 C86.2 C87.2 C88.2 C89.2 C90.2 C91.2 C92.2 C93.2 C94.2 C95.2 C96.2 C97.2 C98.2 C99.2 C100.2 C101.2 C102.2 C103.2 C104.2 C105.2 C106.2 C107.2 C108.2 C109.2 C110.2 C111.2 C112.2 C113.2 C114.2 C115.2 D5.1 J1.2 J1.3 J2.5 J2.6 J2.7 J2.8 J2.9 J2.10 J2.11 J3.2 J3.3 J4.2 J4.3 J4.4 J4.5 J5.2 J5.3 J6.2 J6.3 Q1.2 Q2.2 R2.1 R5.1 R6.1 R8.1 R24.1 R25.1 R30.2 R45.2 R46.2 R56.1 R77.1 R97.1 R98.1 SW1.2 SW2.2 U1.2 U2.2 U3.2 U4.3 U5.5 U5.8 U6.4 U7.19 U7.57 U8.3 U10.4 U11.49 U13.3 U14.2 U14.9 Y1.2 Y2.2 Y2.4 Y4.5 | length 2668.5
  L01-TOP w6: U10.4@275.59,1313.39 U10.4@277.56,1311.42 ; U7.19@768,1610.24 801.57,1610.19 v1(801.66,1610.11) ; v1(1152.35,885.45) 1152.35,841.55 Y4.5@1154.72,839.17
  L01-TOP w10: v1(27.78,841.6) 59.8,841.6 U14.2@59.86,841.54 ; U14.9@129.74,841.54 129.82,841.61 171.38,841.61 v1(171.81,842.04)
  L01-TOP w15: J2.5@190.94,366.14 236.46,366.14 v1(237.21,365.39) ; v1(236.34,594.49) 236.53,594.3 236.53,586.3 C105.2@259.84,562.99 ; v1(354.25,2206.49) 354.33,2206.41 C51.2@354.33,2173.23 ; U8.3@608.27,1994.09 614.78,2000.61 652.55,2000.61 v1(652.74,2000.8)
  L01-TOP w20: U3.2@1110.24,2029.79 1110.24,1990.83 v1(1110.48,1990.58)
  L01-TOP w30: v1(32.87,378.6) 84,378.6 J2.10@84.65,377.95 ; v1(35.43,456.69) J2.9@84.65,456.69
  L10-BOT w6: v1(27.56,1177.17) 90.55,1177.17 99.41,1186.02 R25.1@99.41,1208.66 ; Q2.2@153.54,631.89 226.38,631.89 236.34,621.93 v1(236.34,594.49) ; v1(291.34,1358.27) 293.31,1358.27 R30.2@318.9,1332.68 ; R30.2@309.1,1341.49 310.09,1341.49 R30.2@318.9,1332.68 ; R30.2@318.9,1331.69 R30.2@318.9,1332.68 ; C67.2@322.83,982.23 323.17,982.57 v1(344.49,982.57) ; C83.2@488.19,729.7 495.27,722.62 495.27,702.14 v1(497.03,700.37) ; v1(535.43,641.73) C76.2@535.43,666.71 ; v1(584.97,633.83) 594.37,643.23 C70.2@594.37,657.48 ; v1(612.48,580.7) 614.44,578.74 C60.2@643.09,578.74 ; v1(791.25,603.24) 792.13,604.12 792.13,616.32 C106.2@799.21,623.4
  L10-BOT w12: v1(240.16,1114.17) 241.24,1114.17 245.18,1118.11 R24.1@274.61,1118.11 ; v1(274.61,1082.68) 275.37,1081.91 319.93,1081.91 C66.2@322.92,1078.92 ; v1(349.74,1193.61) 349.74,1172.4 C71.2@358.27,1163.88 ; C64.2@365.1,1082.44 v1(396.16,1082.44) ; v1(374.02,1200.79) 375.1,1200.79 377.12,1202.81 C96.2@404.08,1202.81 ; C95.2@452.61,1202.45 454.09,1200.97 v1(484.64,1200.97) ; C68.2@659.94,748.03 674.89,733.09 v1(674.89,708.92) ; v1(869.63,831.58) 869.93,831.88 897.34,831.88 C114.2@897.64,832.18 ; v1(881.46,729.09) 882.88,727.66 C112.2@908.51,727.66 ; v1(884.18,770.47) 884.52,770.13 C113.2@914.13,770.13 ; C90.2@977.72,1306.2 999,1306.2 1007.76,1314.96 v1(1007.87,1314.96) ; v1(1008.34,1285.07) 1008.34,1261.84 C91.2@1013.76,1256.41 ; C93.2@1014.19,1202.03 1018.27,1206.11 1039.68,1206.11 1042.22,1208.66 v1(1043.31,1208.66) ; C79.2@1041.78,1120.31 v1(1041.78,1141.73) ; C73.2@1048.55,1074.8 1048.55,1036.39 v1(1049.06,1035.87)
  L10-BOT w15: v1(27.78,841.6) 60.3,841.6 62.94,838.96 63.93,838.96 68.24,834.65 R56.1@68.24,833.66 ; C55.2@51.18,1103.72 79.73,1103.72 v1(81.09,1102.36) 80.89,1102.17 Q1.2@80.89,1059.24 ; v1(344.94,1322.84) C111.2@375.37,1322.83 ; v1(351.08,1357.35) 351.27,1357.54 374.65,1357.54 C74.2@375.37,1358.27 ; U13.3@354.33,364.17 354.33,339.09 v1(354.4,339.03) ; v1(381.44,1779.87) C46.2@401.57,1779.87 ; v1(387.52,1657.48) 387.52,1678.86 C39.2@389.76,1681.1 ; v1(389.36,1713.96) 389.76,1714.36 C43.2@389.76,1736.22 ; v1(456.69,1866.14) 456.88,1865.95 464.76,1865.95 C47.2@484.25,1846.46 ; C110.2@458.98,1361.15 458.98,1362.51 461.56,1365.09 475.49,1365.09 483.28,1372.89 v1(483.55,1372.89) ; C33.2@464.57,1460.63 464.57,1487.92 468.5,1491.86 v1(468.5,1492.13) ; C84.2@556.66,1244.94 558.02,1243.58 558.02,1220.3 562.99,1215.33 v1(562.99,1215.06) ; v1(662.37,1368.22) 662.37,1367.95 667.93,1362.38 C72.2@667.93,1334.65 ; C86.2@665.94,1246 665.94,1220.46 667.29,1219.11 v1(667.29,1218.84) ; C72.2@669.29,1334.65 671.87,1332.06 671.87,1312.65 681.1,1303.42 v1(681.1,1303.15) ; v1(677.17,1051.18) C58.2@677.17,1080.22 ; v1(684.76,1356.95) 684.95,1357.14 703.39,1357.14 704.75,1358.5 C100.2@704.75,1359.19 ; v1(685.58,644.14) 685.85,644.14 698.72,631.28 710.02,631.28 712.6,628.7 C108.2@712.6,627.34 703.22,627.34 v1(687.72,611.84) ; C101.2@707.23,1316.46 707.23,1289.89 v1(710.06,1287.06) ; v1(710.96,1230.1) 711.41,1230.54 C103.2@711.41,1257.03 ; C31.2@711.75,1862.2 738.62,1862.2 v1(739.54,1863.13) ; v1(734.41,611.32) 734.68,611.32 742.58,619.21 758.48,619.21 C104.2@759.84,620.57 ; C59.2@744.09,477.29 744.09,475.93 746.68,473.35 748.03,473.35 752.69,468.7 763.59,468.7 v1(763.78,468.5) ; C61.1@834.25,555.12 856.26,533.11 v1(862.76,533.11) ; v1(834.45,1700.79) 834.64,1700.6 834.64,1691.14 C32.2@852.36,1673.41 ; C97.2@861.84,592.12 861.84,575.17 v1(874.02,562.99) ; v1(898.8,1211.66) 899.28,1212.14 C62.2@899.28,1248.42 ; C20.2@921.26,2003.94 933.52,2016.2 933.52,2028.12 v1(933.72,2028.31) ; C7.1@934.06,2212.73 961.2,2212.73 961.85,2213.39 v1(962.12,2213.39) ; v1(997.76,507.87) 1009.57,496.06 1034.31,496.06 ; C77.2@1002.46,1019.68 1027.79,1019.68 v1(1027.91,1019.81) ; C88.2@1025.18,967.29 1051.98,967.29 v1(1052.85,966.42) ; C89.2@1026.05,921.35 v1(1051.18,921.35) ; v1(1027.56,448.82) 1027.56,489.31 1034.31,496.06 ; v1(1062.99,433.07) 1062.99,433.34 1059.06,437.28 C54.1@1059.06,496.06 1034.31,496.06 ; C17.2@1077.86,2326.77 1106.58,2326.77 v1(1107.02,2326.34) ; C19.2@1078.84,2287.4 1102.09,2287.4 1106.03,2291.34 v1(1106.3,2291.34)
  other v1: 43.31,27.56 78.74,27.56 122.05,27.56 157.48,27.56 200.79,27.56 236.22,27.56 275.59,27.56 311.02,27.56 354.33,27.56 389.76,27.56 433.07,27.56 468.5,27.56 511.81,27.56 547.24,27.56 590.55,27.56 625.98,27.56 669.29,27.56 704.72,27.56 748.03,27.56 783.46,27.56 826.77,27.56 862.2,27.56 909.45,27.56 944.88,27.56 988.19,27.56 1023.62,27.56 1066.93,27.56 1102.36,27.56 1145.67,27.56 1181.1,27.56 1212.6,43.31 27.56,68.5 1225.85,79.03 27.56,103.94 1225.85,114.47 1225.85,149.9 27.56,161.42 1225.85,193.21 27.56,196.85 1023.62,228.35 1225.85,228.64 370.08,232.28 574.8,232.28 948.82,232.28 700.79,240.16 1200.79,250 909.45,251.97 370.08,267.72 574.8,267.72 700.79,275.59 909.45,279.53 1225.85,283.76 574.8,295.28 370.08,299.21 700.79,307.09 909.45,307.09 1225.85,319.19 964.43,330.71 1225.9,362.2 383.18,366.63 962.6,368.35 1225.9,397.64 387.01,426.24 1225.9,440.94 1225.9,476.38 779.53,491.68 1225.9,519.68 988.19,555.12 1225.9,555.12 913.39,566.93 988.19,582.68 939.81,594.49 27.56,598.43 1225.9,606.3 988.07,610.24 659.8,619.07 27.56,633.86 1225.9,641.73 826.71,659.67 421.26,664.73 485.03,665.24 460.63,744.09 354.33,755.91 381.89,755.91 559.06,755.91 1225.07,755.84 251.97,759.84 381.89,779.53 251.97,783.46 1225.07,791.27 1225.07,830.64 329.8,854.26 1225.07,866.08 346.46,870.08 370.08,870.08 259.35,881.89 598.43,881.89 632.9,881.89 569.96,883.86 761.81,883.86 715.06,885.83 1098.8,888.77 1225.9,905.51 259.35,907.87 23.99,909.45 751.97,933.07 704.72,940.94 1225.9,940.94 23.99,944.88 645.67,944.88 606.3,952.76 751.97,972.44 1225.9,976.38 23.99,996.04 704.72,1000 751.97,1000 586.61,1001.97 645.67,1003.94 1225.9,1013.25 23.99,1031.48 755.91,1031.5 574.14,1046.34 1225.9,1051.18 609.57,1055.12 702.76,1059.06 761.81,1061.02 643.7,1062.99 26.48,1074.38 1098.43,1078.74 1141.73,1078.74 1225.9,1086.61 23.8,1110.27 1225.9,1122.05 1225.9,1158.92 1225.9,1196.85 1225.9,1232.28 1225.9,1267.72 1078.74,1271.65 1102.36,1271.65 1125.98,1271.65 28.16,1289.41 1225.9,1304.59 27.93,1324.4 1225.9,1338.58 27.14,1365.43 1225.9,1375.46 27.14,1400.86 1225.9,1413.39 27.14,1445.16 1225.9,1448.82 1098.43,1468.5 1141.73,1468.5 27.14,1480.59 1225.9,1484.25 27.14,1518.97 1225.9,1521.13 27.14,1554.41 1225.9,1555.12 1225.9,1591.99 582.68,1598.43 681.1,1598.43 27.14,1598.7 1225.9,1629.92 27.14,1634.13 633.86,1653.54 582.68,1657.48 1225.9,1665.35 27.14,1680.39 582.68,1700.79 681.1,1700.79 1225.9,1700.79 27.14,1715.82 1225.9,1737.66 1118.11,1740.16 1066.31,1740.69 1094.49,1740.69 27.14,1760.12 1225.9,1771.65 27.14,1795.55 1225.9,1808.53 385.83,1834.65 437.01,1834.65 24.04,1840.86 1225.9,1846.46 24.04,1876.3 972.44,1877.95 1225.9,1881.89 929.13,1917.32 1011.81,1917.32 1225.9,1917.32 24.04,1920.59 1066.41,1930.14 1100.41,1930.77 1225.9,1954.2 24.04,1956.02 1225.9,1988.19 28.31,1994.12 1015.75,2007.87 964.57,2015.75 1225.9,2025.06 28.64,2026.97 27.56,2055.12 1225.9,2062.99 27.56,2095.38 1225.9,2098.43 972.44,2118.11 27.9,2128.23 1225.9,2133.86 885,2141.73 26.81,2156.38 1225.9,2170.73 27.67,2188.52 1224.41,2196.85 27.56,2224.41 1224.41,2232.28 1224.41,2267.72 24.5,2273.65 1224.41,2291.34 24.83,2306.49 728.35,2318.9 1224.41,2326.77 23.75,2334.65 740.16,2358.27 1224.41,2362.2 24.61,2366.79 623.03,2370.08 593.5,2374.02 649.61,2377.95 669.29,2397.64 740.16,2397.64 574.8,2401.57 1212.6,2401.57 24.5,2402.67 700.79,2417.32 559.06,2421.26 1220.47,2425.2 732.28,2433.07 26.3,2451.73 1220.47,2460.63 26.3,2479.29 1222.92,2499.49 26.3,2514.72 555.12,2529.6 1220.47,2534.92 598.43,2539.37 26.3,2550.15 625.98,2551.18 653.54,2566.93 688.98,2570.87 1224.41,2574.8 28.11,2586.61 724.41,2586.61 799.21,2586.61 858.27,2586.61 897.64,2586.61 937.01,2586.61 759.84,2590.55 1216.44,2611.14 98.43,2618.11 133.86,2618.11 169.29,2618.11 204.72,2618.11 566.93,2618.11 602.36,2618.11 629.92,2618.11 665.35,2618.11 704.72,2618.11 740.16,2618.11 783.46,2618.11 818.9,2618.11 846.46,2618.11 881.89,2618.11 921.26,2618.11 956.69,2618.11 992.13,2618.11 1027.56,2618.11 1055.12,2618.11 1090.55,2618.11 1129.92,2618.11 1165.35,2618.11
NEOPIXEL: U7.27 U8.4 | length 710.4
  L01-TOP w6: U8.4@608.27,2124.02 655.51,2124.02 732.28,2047.24 v1(732.28,1905.51) ; U7.27@768.14,1736.22 890.91,1736.22 921.26,1766.57 v1(921.26,1767.72)
  L03-SIG w5.5: v1(732.28,1905.51) 783.46,1905.51 v1(921.26,1767.72)
NetC2_2: C2.2 R1.2 R2.2 | length 80.7
  L01-TOP w6: C2.2@657.48,2493.31 662.2,2498.03 R1.2@736.22,2498.03
NetC4_1: C4.1 L1.2 R1.1 U1.5 | length 119.5
  L01-TOP w6: R1.1@736.22,2533.46 743.11,2526.57 C4.1@775.59,2526.57 807.23,2526.57 L1.2@811.02,2522.78 811.87,2523.62 U1.5@850.98,2523.62
NetC5_1: C5.1 C6.2 C8.1 L1.1 R4.1 R5.2 | length 217.9
  L01-TOP w6: R4.1@806.1,2279.53 803.15,2282.48 R5.2@803.15,2322.83 803.15,2408.44 804.72,2410.01 804.72,2486.67 L1.1@811.02,2492.97
NetC21_1: C21.1 R3.1 R7.2 R8.2 | length 144.9
  L01-TOP w6: C21.1@893.7,435.65 898.01,439.96 R3.1@940.94,439.96 R8.2@940.94,489.17 947.21,482.91 R7.2@984.97,482.91
NetC24_1: C24.1 C25.1 C26.1 C27.1 L2.2 Y1.4
NetC53_2: C53.2 R14.1 Y2.3 | length 162.4
  L01-TOP w6: R14.1@896.65,1641.73 893.7,1644.69 893.7,1697.27 897.22,1700.79 C53.2@916.93,1700.79 925.2,1692.52 925.2,1673.23 930.17,1668.26 930.17,1654.48 Y2.3@950.79,1633.86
